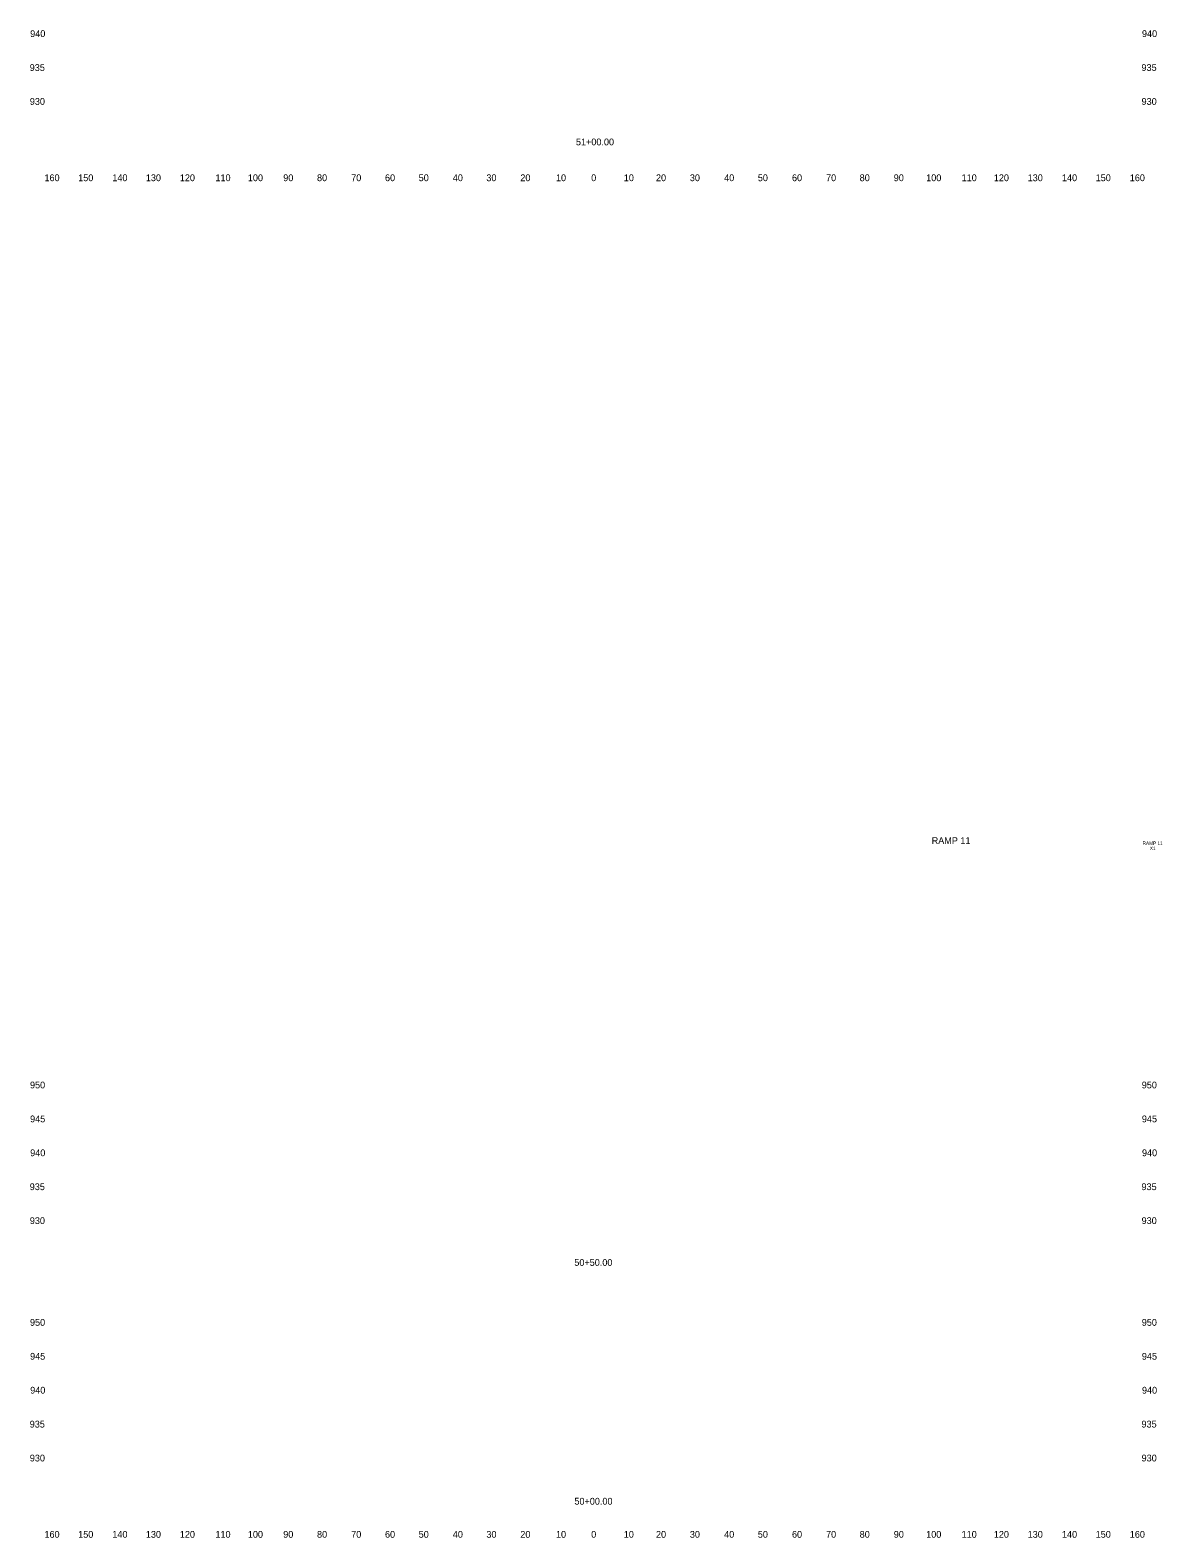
# Model space of a CAD drawing. Extents: x 4994 to 5843, y 4997 to 8804.
# Drawn here: x 4993.9 to 5327.6, y 4997.5 to 5442 of the extents above; entities that cross this region are included whole.
import ezdxf

# ---------------------------------------------------------------- set-up
doc = ezdxf.new("R2010")
doc.units = 0
for name, color, linetype in [('RD_SHT_ID', 7, 'Continuous'), ('RD_XS_TX_Offset', 7, 'Continuous'), ('RD_XS_TX_Station', 7, 'Continuous')]:
    doc.layers.add(name, color=color, linetype=linetype)

msp = doc.modelspace()

# ---------------------------------------------------------------- texts
at = {"layer": 'RD_SHT_ID'}
for s, height, p in [('RAMP 11', 2, (5259.69, 5202.06)), ('RAMP 11', 1, (5321.89, 5201.8)), ('X1', 1, (5324.02, 5200.3))]:
    msp.add_text(s, height=height, dxfattribs=at).set_placement(p)
at = {"layer": 'RD_XS_TX_Offset'}
for s, p in [('940', (4993.89, 5440)), ('940', (5321.69, 5440)), ('935', (4993.75, 5430)), ('935', (5321.55, 5430)), ('930', (4993.78, 5420)), ('930', (5321.58, 5420)), ('160', (4998.1, 5397.5)), ('150', (5008.04, 5397.5)), ('140', (5018.1, 5397.5)), ('130', (5027.99, 5397.5)), ('120', (5038.01, 5397.5)), ('110', (5048.51, 5397.5)), ('100', (5058.07, 5397.5)), ('90', (5068.5, 5397.5)), ('80', (5078.46, 5397.5)), ('70', (5088.54, 5397.5)), ('60', (5098.5, 5397.5)), ('50', (5108.43, 5397.5)), ('40', (5118.5, 5397.5)), ('30', (5128.39, 5397.5)), ('20', (5138.4, 5397.5)), ('10', (5148.91, 5397.5)), ('0', (5159.3, 5397.5)), ('0', (5159.3, 5397.5)), ('10', (5168.91, 5397.5)), ('20', (5178.4, 5397.5)), ('30', (5188.39, 5397.5)), ('40', (5198.5, 5397.5)), ('50', (5208.43, 5397.5)), ('60', (5218.5, 5397.5)), ('70', (5228.54, 5397.5)), ('80', (5238.46, 5397.5)), ('90', (5248.5, 5397.5)), ('100', (5258.07, 5397.5)), ('110', (5268.51, 5397.5)), ('120', (5278.01, 5397.5)), ('130', (5287.99, 5397.5)), ('140', (5298.1, 5397.5)), ('150', (5308.04, 5397.5)), ('160', (5318.1, 5397.5)), ('950', (4993.83, 5130)), ('950', (5321.63, 5130)), ('945', (4993.86, 5120)), ('945', (5321.66, 5120)), ('940', (4993.89, 5110)), ('940', (5321.69, 5110)), ('935', (4993.75, 5100)), ('935', (5321.55, 5100)), ('930', (4993.78, 5090)), ('930', (5321.58, 5090)), ('950', (4993.83, 5060)), ('950', (5321.63, 5060)), ('945', (4993.86, 5050)), ('945', (5321.66, 5050)), ('940', (4993.89, 5040)), ('940', (5321.69, 5040)), ('935', (4993.75, 5030)), ('935', (5321.55, 5030)), ('930', (4993.78, 5020)), ('930', (5321.58, 5020)), ('160', (4998.1, 4997.5)), ('150', (5008.04, 4997.5)), ('140', (5018.1, 4997.5)), ('130', (5027.99, 4997.5)), ('120', (5038.01, 4997.5)), ('110', (5048.51, 4997.5)), ('100', (5058.07, 4997.5)), ('90', (5068.5, 4997.5)), ('80', (5078.46, 4997.5)), ('70', (5088.54, 4997.5)), ('60', (5098.5, 4997.5)), ('50', (5108.43, 4997.5)), ('40', (5118.5, 4997.5)), ('30', (5128.39, 4997.5)), ('20', (5138.4, 4997.5)), ('10', (5148.91, 4997.5)), ('0', (5159.3, 4997.5)), ('0', (5159.3, 4997.5)), ('10', (5168.91, 4997.5)), ('20', (5178.4, 4997.5)), ('30', (5188.39, 4997.5)), ('40', (5198.5, 4997.5)), ('50', (5208.43, 4997.5)), ('60', (5218.5, 4997.5)), ('70', (5228.54, 4997.5)), ('80', (5238.46, 4997.5)), ('90', (5248.5, 4997.5)), ('100', (5258.07, 4997.5)), ('110', (5268.51, 4997.5)), ('120', (5278.01, 4997.5)), ('130', (5287.99, 4997.5)), ('140', (5298.1, 4997.5)), ('150', (5308.04, 4997.5)), ('160', (5318.1, 4997.5))]:
    msp.add_text(s, height=2, dxfattribs=at).set_placement(p)
at = {"layer": 'RD_XS_TX_Station'}
for s, p in [('51+00.00', (5154.8, 5408.07)), ('50+50.00', (5154.32, 5077.67)), ('50+00.00', (5154.35, 5007.27))]:
    msp.add_text(s, height=2, dxfattribs=at).set_placement(p)

doc.saveas('drawing.dxf')
